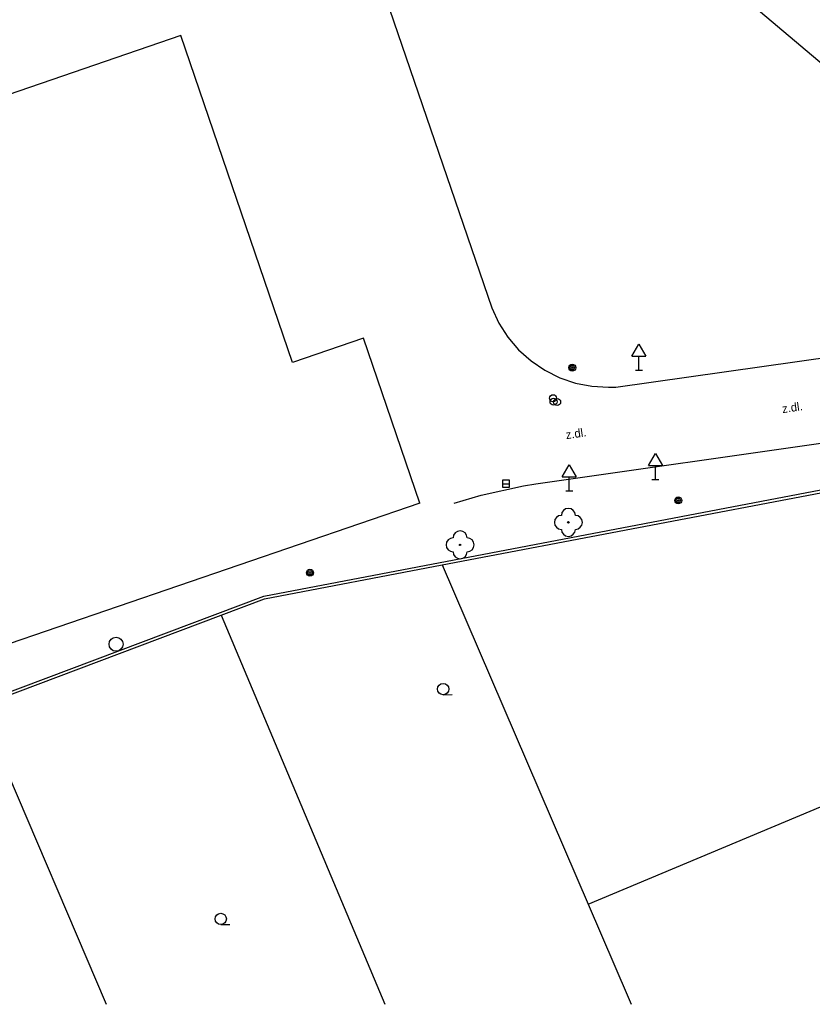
# Model space of a CAD drawing. Extents: x -640201 to -639641, y -1044739 to -1044317.
# Drawn here: x -639987.9 to -639931.2, y -1044738.7 to -1044668.4 of the extents above; entities that cross this region are included whole.
import ezdxf

# ---------------------------------------------------------------- set-up
doc = ezdxf.new("R2010")
doc.units = 0
for name, color, linetype in [('Budovy', 7, 'Continuous'), ('Ploty', 7, 'Continuous'), ('Popis povrchů', 7, 'Continuous'), ('Rozhraní ploch 1', 7, 'Continuous'), ('Rozhraní ploch 2', 7, 'Continuous'), ('Sloupy_označník', 7, 'Continuous'), ('Zeleň - stromy', 7, 'Continuous'), ('Znaky kanalizace', 7, 'Continuous'), ('Znaky voda', 7, 'Continuous'), ('Značky doprava', 7, 'Continuous'), ('Značky KM', 7, 'Continuous')]:
    doc.layers.add(name, color=color, linetype=linetype)

msp = doc.modelspace()

# ---------------------------------------------------------------- linework, layer by layer
at = {"layer": 'Budovy'}
for p, q in [((-639976.34, -1044669.49), (-640038.53, -1044690.8)), ((-639968.36, -1044692.85), (-639976.34, -1044669.49)), ((-639963.28, -1044691.12), (-639968.36, -1044692.85)), ((-639959.258, -1044702.919), (-639963.28, -1044691.12)), ((-639959.258, -1044702.919), (-640030.256, -1044727.186))]:
    msp.add_line(p, q, dxfattribs=at)
at = {"layer": 'Ploty'}
for p, q in [((-639970.42, -1044709.55), (-639905.5, -1044697.19)), ((-639957.654, -1044707.322), (-639905.463, -1044697.386)), ((-639970.365, -1044709.742), (-639957.654, -1044707.322)), ((-640007.01, -1044723.32), (-639970.42, -1044709.55)), ((-639973.459, -1044710.907), (-639970.365, -1044709.742)), ((-639990.801, -1044717.434), (-639973.459, -1044710.907)), ((-639973.459, -1044710.907), (-639961.755, -1044738.718)), ((-639990.801, -1044717.434), (-639981.685, -1044738.718))]:
    msp.add_line(p, q, dxfattribs=at)
at = {"layer": 'Rozhraní ploch 1'}
for p, q in [((-639971.06, -1044639.55), (-639954.11, -1044688.96)), ((-639963.01, -1044643.95), (-639919.01, -1044681.27)), ((-639945.24, -1044694.61), (-639908.79, -1044689.48)), ((-639950.96, -1044701.52), (-639912.29, -1044696))]:
    msp.add_line(p, q, dxfattribs=at)
for points in [[(-639954.11, -1044688.96), (-639953.607, -1044690.039), (-639952.965, -1044691.041), (-639952.194, -1044691.948), (-639951.308, -1044692.743), (-639950.324, -1044693.413), (-639949.26, -1044693.945), (-639948.133, -1044694.329), (-639946.965, -1044694.559)], [(-639946.965, -1044694.559), (-639945.777, -1044694.63), (-639945.24, -1044694.61)], [(-639956.8, -1044702.905), (-639954.868, -1044702.327), (-639951.835, -1044701.666), (-639950.96, -1044701.52)]]:
    msp.add_lwpolyline(points, dxfattribs=at)
at = {"layer": 'Rozhraní ploch 2'}
for p, q in [((-639957.654, -1044707.322), (-639947.23, -1044731.56)), ((-639947.23, -1044731.56), (-639920.85, -1044720.5)), ((-639947.23, -1044731.56), (-639944.37, -1044738.2))]:
    msp.add_line(p, q, dxfattribs=at)
msp.add_lwpolyline([(-639944.37, -1044738.2), (-639944.147, -1044738.718)], dxfattribs=at)
at = {"layer": 'Sloupy_označník'}
for centre, radius in [((-639948.36, -1044693.23), 0.25), ((-639948.36, -1044693.23), 0.158), ((-639948.36, -1044693.23), 0.05), ((-639940.78, -1044702.71), 0.25), ((-639940.78, -1044702.71), 0.158), ((-639940.78, -1044702.71), 0.05), ((-639967.11, -1044707.88), 0.25), ((-639967.11, -1044707.88), 0.158), ((-639967.11, -1044707.88), 0.05)]:
    msp.add_circle(centre, radius, dxfattribs=at)
at = {"layer": 'Zeleň - stromy'}
for centre in [(-639948.64, -1044704.28), (-639956.38, -1044705.89)]:
    msp.add_circle(centre, 0.05, dxfattribs=at)
for centre, start, end in [((-639948.64, -1044703.78), 0, 180), ((-639949.14, -1044704.28), 90, 270), ((-639948.14, -1044704.28), 270, 90), ((-639956.38, -1044705.39), 0, 180), ((-639948.64, -1044704.78), 180, 0), ((-639956.88, -1044705.89), 90, 270), ((-639955.88, -1044705.89), 270, 90), ((-639956.38, -1044706.39), 180, 0)]:
    msp.add_arc(centre, 0.5, start, end, dxfattribs=at)
at = {"layer": 'Znaky kanalizace'}
msp.add_line((-639953.35, -1044701.524), (-639952.85, -1044701.524), dxfattribs=at)
msp.add_lwpolyline([(-639953.35, -1044701.774), (-639952.85, -1044701.774), (-639952.85, -1044701.274), (-639953.35, -1044701.274)], close=True, dxfattribs=at)
msp.add_circle((-639980.978, -1044712.991), 0.5, dxfattribs=at)
at = {"layer": 'Znaky voda'}
for centre in [(-639949.73, -1044695.41), (-639949.7, -1044695.66), (-639949.44, -1044695.68)]:
    msp.add_circle(centre, 0.25, dxfattribs=at)
at = {"layer": 'Značky doprava'}
for p, q in [((-639944.1, -1044692.41), (-639943.6, -1044691.56)), ((-639943.6, -1044691.56), (-639943.1, -1044692.41)), ((-639944.1, -1044692.41), (-639943.1, -1044692.41)), ((-639943.6, -1044693.41), (-639943.6, -1044692.41)), ((-639943.85, -1044693.41), (-639943.35, -1044693.41)), ((-639942.92, -1044700.21), (-639942.42, -1044699.36)), ((-639942.42, -1044699.36), (-639941.92, -1044700.21)), ((-639949.08, -1044701.02), (-639948.58, -1044700.17)), ((-639948.58, -1044700.17), (-639948.08, -1044701.02)), ((-639942.92, -1044700.21), (-639941.92, -1044700.21)), ((-639942.42, -1044701.21), (-639942.42, -1044700.21)), ((-639949.08, -1044701.02), (-639948.08, -1044701.02)), ((-639948.58, -1044702.02), (-639948.58, -1044701.02)), ((-639942.67, -1044701.21), (-639942.17, -1044701.21)), ((-639948.83, -1044702.02), (-639948.33, -1044702.02))]:
    msp.add_line(p, q, dxfattribs=at)
at = {"layer": 'Značky KM'}
for p, q in [((-639957.591, -1044716.595), (-639956.941, -1044716.592)), ((-639973.492, -1044733.02), (-639972.842, -1044733.017))]:
    msp.add_line(p, q, dxfattribs=at)
for centre in [(-639957.591, -1044716.192), (-639973.492, -1044732.617)]:
    msp.add_circle(centre, 0.403, dxfattribs=at)

# ---------------------------------------------------------------- texts
at = {"layer": 'Popis povrchů'}
for p in [(-639933.316, -1044696.476), (-639948.784, -1044698.336)]:
    msp.add_text('z.dl.', height=0.6, rotation=8.12388, dxfattribs=at).set_placement(p)

doc.saveas('drawing.dxf')
